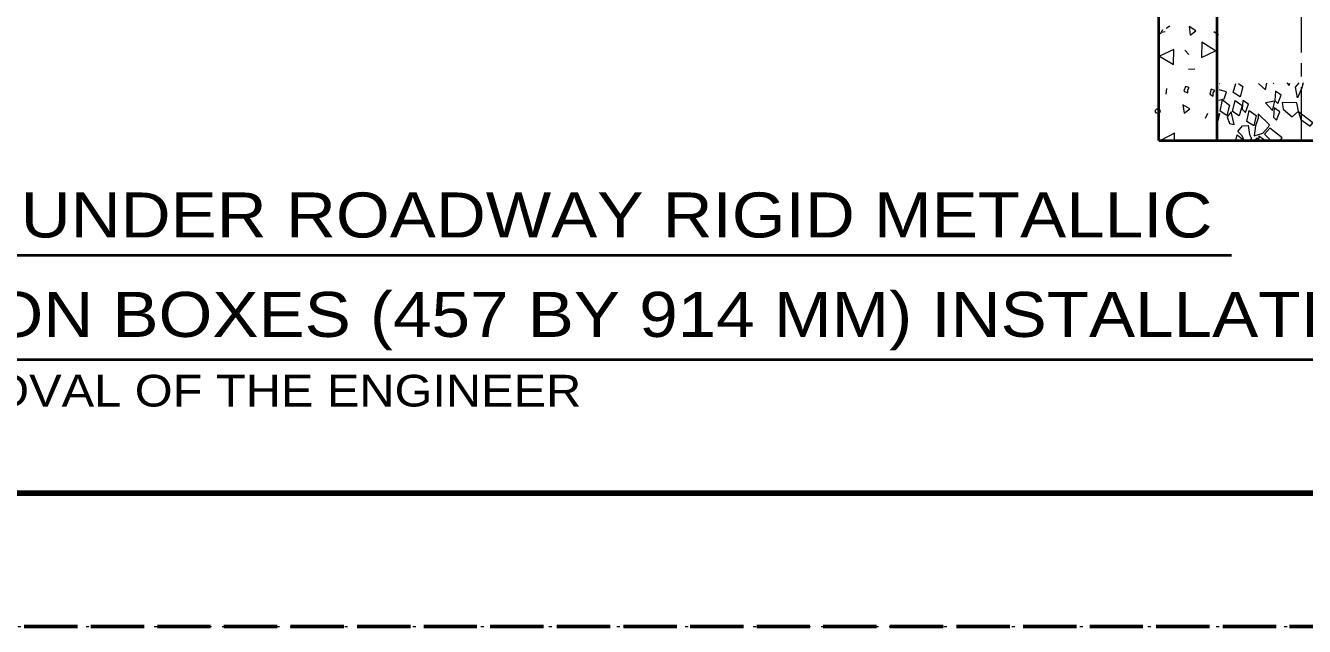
# Model space of a CAD drawing. Extents: x 312583 to 312854, y 144419 to 144597.
# Drawn here: x 312670 to 312713.21, y 144418.58 to 144438.88 of the extents above; entities that cross this region are included whole.
import ezdxf
from ezdxf.enums import TextEntityAlignment as Align

# ---------------------------------------------------------------- set-up
doc = ezdxf.new("R2010")
doc.units = 0
doc.header["$LTSCALE"] = 0.3
for name, pattern in [('DOTTED', [1.5, 0.3, -1.2]), ('LONG_DASH_SHORT_DASH', [9.9, 6, -1.2, 1.5, -1.2]), ('LONG_DASHED', [7.5, 6, -1.5])]:
    doc.linetypes.add(name, pattern=pattern)
for name, color, linetype, lineweight in [('1', 7, 'Continuous', 40), ('2', 7, 'Continuous', 13), ('63', 7, 'DOTTED', 13)]:
    doc.layers.add(name, color=color, linetype=linetype, lineweight=lineweight)

msp = doc.modelspace()

# ---------------------------------------------------------------- linework, layer by layer
at = {"layer": '1'}
msp.add_line((312708.2912, 144434.9934), (312717.9205, 144434.9934), dxfattribs=at)
at = {"layer": '1', "lineweight": 158}
msp.add_line((312616.5, 144423.0846), (312849, 144423.0846), dxfattribs=at)
at = {"layer": '1', "linetype": 'LONG_DASHED', "lineweight": 60}
msp.add_line((312851.75, 144418.5846), (312583.526, 144418.5846), dxfattribs=at)
at = {"layer": '2', "linetype": 'LONG_DASH_SHORT_DASH'}
msp.add_line((312713.1058, 144434.9934), (312713.1058, 144448.0037), dxfattribs=at)
at = {"layer": '2', "lineweight": 40}
for p, q in [((312708.2912, 144434.9934), (312708.2912, 144440.6361)), ((312710.2538, 144434.9934), (312710.2538, 144440.3064)), ((312638.1714, 144431.1251), (312710.7439, 144431.1251)), ((312718.444, 144427.5906), (312630.5394, 144427.5906))]:
    msp.add_line(p, q, dxfattribs=at)
at = {"layer": '2'}
for p, q in [((312708.5288, 144438.7961), (312708.6592, 144438.8651)), ((312708.4138, 144438.7347), (312708.3372, 144438.5891)), ((312708.3602, 144438.6581), (312708.5058, 144438.6811)), ((312710.1465, 144438.6734), (312710.2998, 144438.5661)), ((312709.1652, 144438.0524), (312709.2955, 144437.8991)), ((312709.2878, 144437.4084), (312709.5025, 144437.4161)), ((312708.5288, 144436.5651), (312708.5518, 144436.7567)), ((312710.3382, 144436.7107), (312710.3305, 144436.6877)), ((312710.3382, 144436.9177), (312710.3458, 144436.9254)), ((312710.7982, 144436.6187), (312710.8825, 144436.9254)), ((312712.8988, 144436.8027), (312713.0292, 144436.9407)), ((312709.9318, 144435.9134), (312709.8475, 144435.7447)), ((312711.6645, 144435.1391), (312711.6568, 144434.9934)), ((312713.1058, 144434.9934), (312713.1058, 144434.9704))]:
    msp.add_line(p, q, dxfattribs=at)
for points in [[(312709.3415, 144438.5584), (312709.5408, 144438.7041), (312709.3108, 144438.8497)], [(312708.7818, 144437.5617), (312708.7895, 144438.0754), (312708.3142, 144437.8454)], [(312709.7402, 144438.3207), (312709.7325, 144437.7994), (312710.2002, 144438.0294)], [(312709.2648, 144436.7107), (312709.3108, 144436.7874), (312709.1882, 144436.8257), (312709.1268, 144436.6647), (312709.2648, 144436.6034)], [(312710.1235, 144436.6111), (312710.1772, 144436.6877), (312710.0545, 144436.7261), (312710.0085, 144436.5651), (312710.1235, 144436.4961)], [(312710.3535, 144435.9901), (312710.4378, 144436.3657), (312710.6755, 144436.1894), (312710.5835, 144435.8444)], [(312710.7752, 144435.9747), (312710.8672, 144436.3504), (312711.0972, 144436.1741), (312711.0052, 144435.8291)], [(312711.1202, 144436.3504), (312711.1048, 144436.0514), (312711.2122, 144435.9441), (312711.3118, 144436.2201)], [(312711.8868, 144436.2661), (312712.1322, 144436.0131), (312712.2088, 144436.3274)], [(312712.2242, 144436.6647), (312712.2088, 144436.3504), (312712.3085, 144436.2431), (312712.4158, 144436.5267)], [(312712.4848, 144436.0514), (312712.7915, 144435.7984), (312713.0062, 144435.9901), (312712.9525, 144436.2737), (312712.4542, 144436.2814)], [(312709.1422, 144435.9211), (312709.3338, 144436.0667), (312709.0962, 144436.2047)], [(312710.5988, 144435.7984), (312710.6755, 144435.5761), (312710.8365, 144435.5377), (312710.7292, 144435.9594)], [(312711.2582, 144435.6374), (312711.3425, 144436.0131), (312711.5802, 144435.8444), (312711.4958, 144435.4917)], [(312711.6415, 144435.7524), (312711.5495, 144435.4917), (312711.5112, 144435.1544), (312711.7948, 144435.2464), (312711.9865, 144435.4611), (312712.0248, 144435.5224), (312711.6415, 144435.8981)], [(312712.1782, 144436.0974), (312712.1628, 144435.7831), (312712.2625, 144435.6834), (312712.3698, 144435.9594)], [(312713.0828, 144435.7064), (312713.4048, 144435.4764), (312713.4892, 144435.5914), (312713.0062, 144435.9671)]]:
    msp.add_lwpolyline(points, close=True, dxfattribs=at)
for points in [[(312710.3152, 144436.3581), (312710.4915, 144436.4041), (312710.5682, 144436.6417), (312710.3382, 144436.7107)], [(312710.9822, 144436.9254), (312711.1202, 144436.8257), (312711.0358, 144436.4731), (312710.7982, 144436.6187)], [(312711.6568, 144436.9254), (312711.8868, 144436.7107), (312711.9405, 144436.9331)], [(312712.1475, 144436.9407), (312712.1628, 144436.9254), (312712.1705, 144436.9331)], [(312712.6152, 144436.9407), (312712.6918, 144436.8564), (312712.7072, 144436.9331)], [(312713.1672, 144436.9407), (312713.1212, 144436.7721), (312712.9678, 144436.4424), (312712.8988, 144436.8027)], [(312710.2922, 144435.8751), (312710.3382, 144435.9134), (312710.2845, 144435.6604)], [(312711.1738, 144434.9934), (312711.0972, 144435.1544), (312710.9515, 144435.3001), (312711.1125, 144435.4917), (312711.3042, 144435.4994), (312711.3502, 144435.2004), (312711.4192, 144435.0624), (312711.3502, 144434.9934)], [(312712.0325, 144435.4151), (312711.8562, 144435.2157), (312712.0708, 144434.9934)], [(312712.3852, 144435.0011), (312712.4542, 144435.0854), (312712.0325, 144435.4151)], [(312708.8125, 144434.9934), (312708.8202, 144435.2387), (312708.3448, 144435.0011), (312708.3525, 144434.9934)], [(312710.8902, 144434.9934), (312710.9285, 144435.1851), (312711.1585, 144435.0087), (312711.1662, 144434.9934)], [(312711.5188, 144434.9934), (312711.6108, 144435.0854), (312711.5955, 144434.9934)], [(312711.8485, 144434.9934), (312711.8562, 144435.0087), (312711.6645, 144435.1391)], [(312711.9098, 144434.9934), (312711.9098, 144435.0317), (312711.9712, 144434.9934)], [(312712.8682, 144435.0011), (312712.8682, 144435.0087), (312712.8835, 144435.0011)]]:
    msp.add_lwpolyline(points, dxfattribs=at)
msp.add_circle((312708.2519, 144435.9913), 0.0785, dxfattribs=at)
at = {"layer": '63'}
msp.add_lwpolyline([(312601.2, 144418.5846), (312853.5, 144418.5846), (312853.5, 144596.7846)], dxfattribs=at)

# ---------------------------------------------------------------- texts
at = {"layer": '2', "width": 1.15}
for s, height, p in [('TYPICAL INSTALLATION OF UNDER ROADWAY RIGID METALLIC', 1.52, (312674.183, 144431.7205)), ('CONDUITS AND TYPICAL JUNCTION BOXES (457 BY 914 MM) INSTALLATION', 1.52, (312674.431, 144428.3625)), ('SUBJECT TO APPROVAL OF THE ENGINEER', 1.07, (312671.2173, 144426.012))]:
    msp.add_text(s, height=height, dxfattribs=at).set_placement(p, align=Align.CENTER)

doc.saveas('drawing.dxf')
